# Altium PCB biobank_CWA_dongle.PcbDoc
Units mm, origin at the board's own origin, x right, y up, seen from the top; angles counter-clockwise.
Board outline 85 x 40 mm, 2 copper layers (Top Layer, Bottom Layer); 24 components, 27 nets, 138 pads, 60 vias.
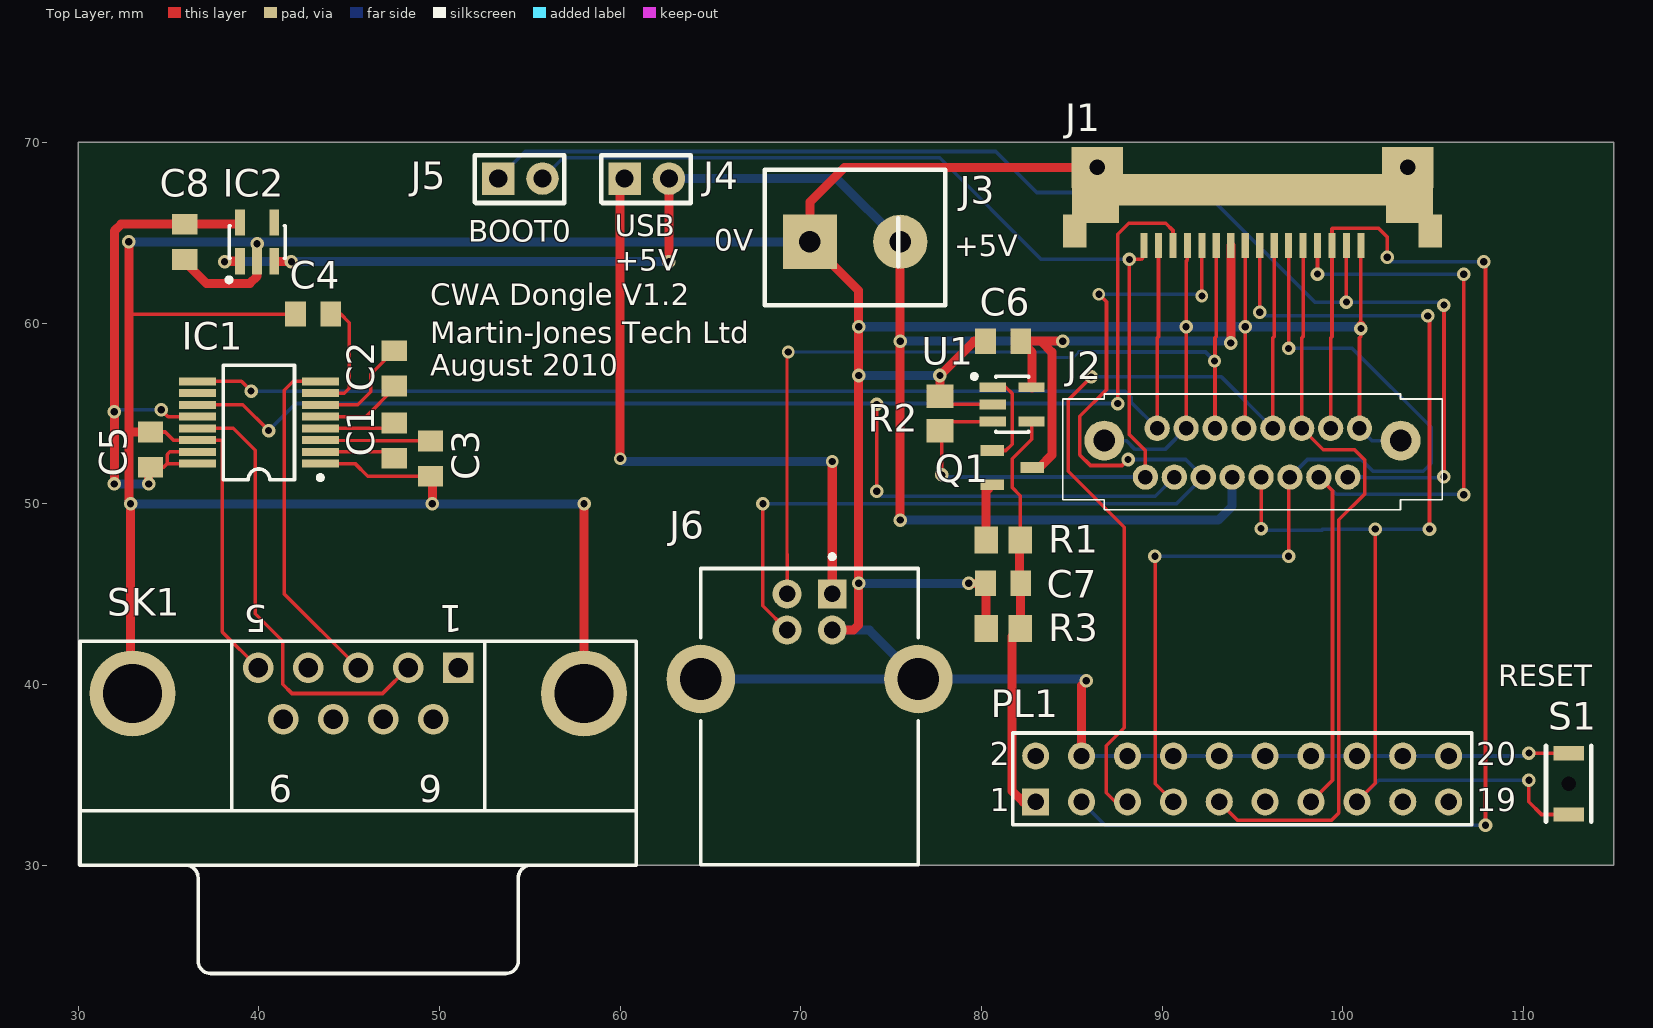
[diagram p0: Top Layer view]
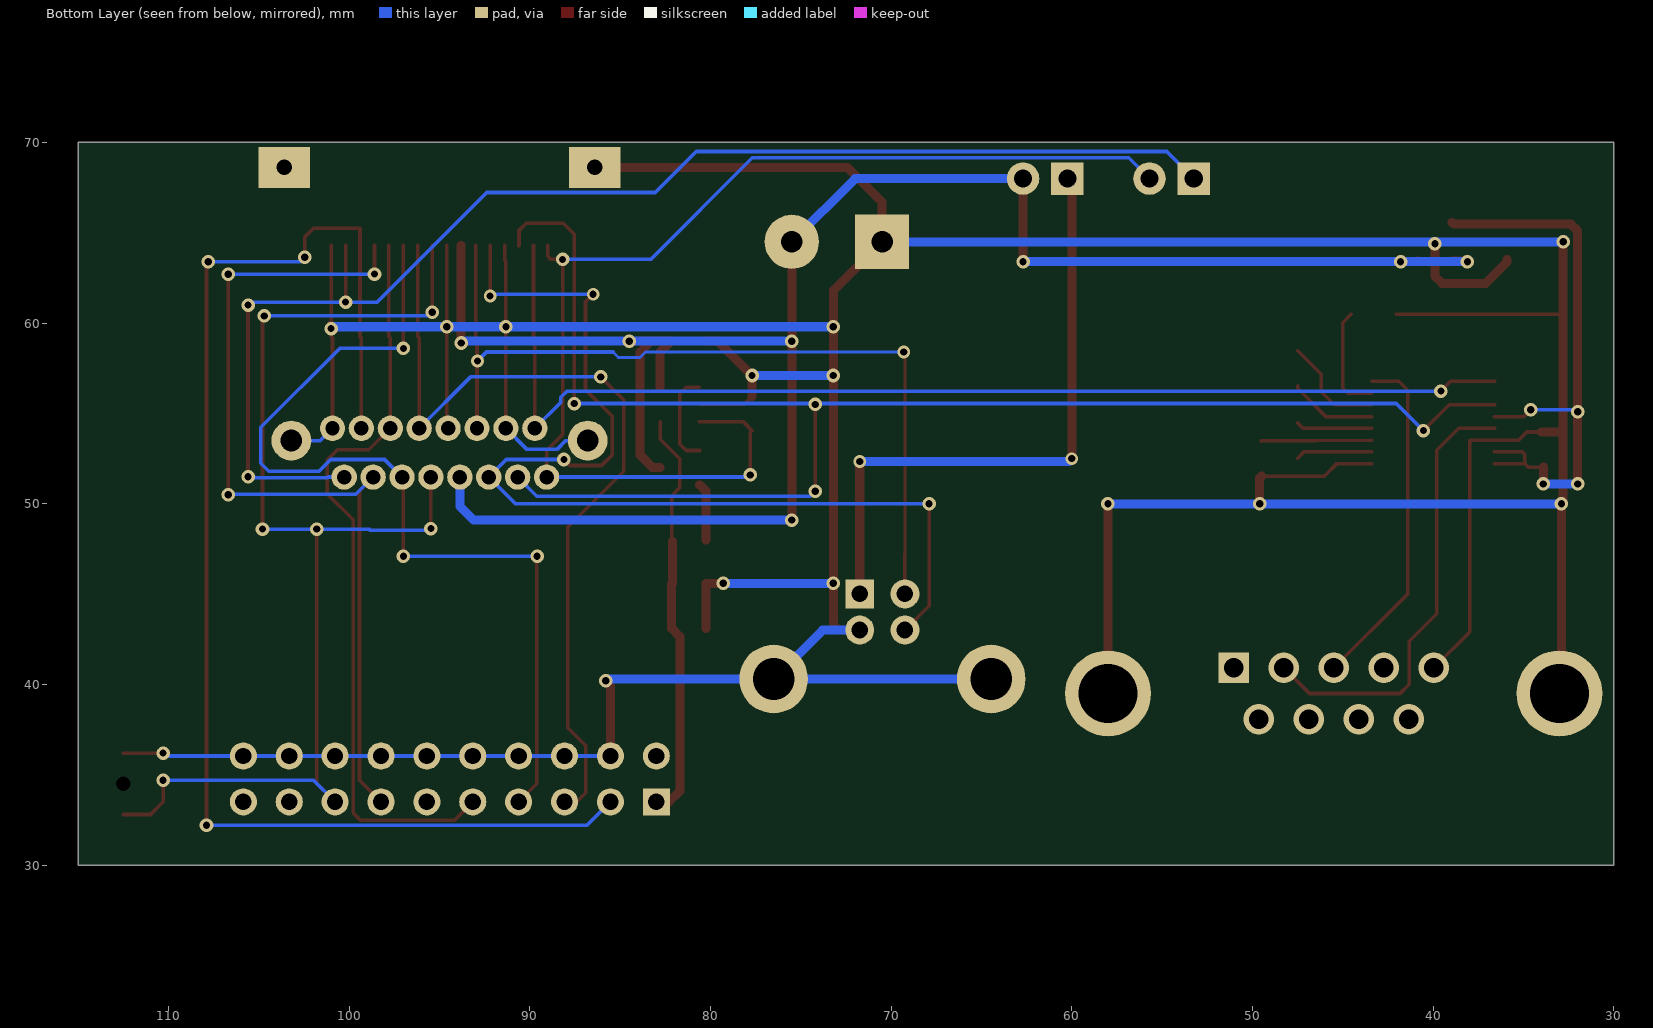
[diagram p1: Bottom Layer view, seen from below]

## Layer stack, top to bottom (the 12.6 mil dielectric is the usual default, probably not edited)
Top Layer: signal copper 0.0356
Dielectric: dielectric 0.32, FR-4, Dk 4.8
Bottom Layer: signal copper 0.0356

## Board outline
30,30 115,30 115,70 30,70

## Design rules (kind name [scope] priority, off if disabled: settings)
Clearance [All] p1: gap=0.15
FabricationTestPointUsage TestPointUsage [All] p1: valid=0 allowmultiple=FALSE
FabricationTestpoint Testpoint [All] p1: side=3 testpointundercomponent=TRUE minsize=1.016 maxsize=2.54 preferedsize=1.524 minholesize=0 maxholesize=1.016 preferedholesize=0.813 testpointgrid=0.025 allowsidetop=TRUE allowsidebottom=TRUE usegrid=TRUE gridtolerance=0
HoleSize [All] p1: absolutevalues=TRUE maxlimit=4 minlimit=0.025 maxpercent=80.000 minpercent=20.000
PolygonConnect [All] p1: connectstyle=Relief reliefconductorwidth=0.254 reliefentries=4 polygonreliefangle="90 Angle"
RoomDefinition biobank_CWA_dongle [InComponentClass('biobank_CWA_dongle')] p1: confinementstyle=ConfineIn formatcopy=TRUE lockcomponents=FALSE outline 29,23 115,23 115,71 29,71
RoutingVias [All] p1: holewidth=0.4 width=0.75 viastyle="Through Hole" minholewidth=0.3 minwidth=0.5 maxholewidth=0.8 maxwidth=1.5
SilkscreenOverComponentPads [All] p1: minsilkscreentomaskgap=0.254
SolderMaskExpansion [All] p1: expansion=0.102
Width [All] p1: maxlimit=1 minlimit=0.15 preferedwidth=0.5 bottomlayer_prefwidth=0.15 minimp=50.000000 maximp=50.000000 favimp=50.000000
24 further rules are at their usual default settings.

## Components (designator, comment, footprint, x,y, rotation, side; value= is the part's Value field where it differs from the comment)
C1 "" 0805-NP 47.5,53.5 r270 top
C2 "" 0805-NP 47.5,57.5 r90 top
C3 "" 0805-NP 49.5,52.5 r90 top
C4 "" 0805-NP 43,60.5 r180 top
C5 "" 0805-NP 34,53 r90 top
C6 "" 0805-NP 81.2,59 r0 top
C7 "" 0805-NP 81.2,45.6 r0 top
C8 "C_0805_4u7_X5R" 0805-NP 35.9,64.5 r90 top
IC1 "*" SSO-G16/X.45 40,54.5 r90 top
IC2 "TPS76333DBVT" SOT23-5 39.9,64.5 r0 top
J1 "CONN_HANDYLINK_16_0.8_MOLEX" HANDYLINK_16 95,65 r0 top
J2 "CONN_HANDYLINK_MALE_16_0.8_MOLEX" MOLEX_4559316xx 95,53.5 r0 top
J3 "*" 2WAY_5MM_TERMINAL 73,64.5 r0 top
J4 "CONN_2_PIN_0.1" 2WAY_0.1 61.5,68 r0 top
J5 "CONN_2_PIN_0.1" 2WAY_0.1 54.5,68 r0 top
J6 "USB slave" USB_B 70.5,44 r270 top
PL1 "" HDR2X10 83,33.5 r0 top
Q1 "BSS138N" SOT23-3 81.7,52 r270 top
R1 "R_0R_0805_1_MULTICOMP" CR2012-0805 81.2,48 r180 top
R2 "R_1M0_0805_1_MULTICOMP_1" CR2012-0805 77.7,55 r270 top
R3 "R_10K_0805_1_MULTICOMP" CR2012-0805 81.2,43.1 r0 top
S1 "" OMRON_B3U_B 112.5,34.5 r270 top
SK1 "" DSUB1.385-2H9 45.5,30 r180 top
U1 "FAN4174" SOT23-5 81.7,55.5 r270 top

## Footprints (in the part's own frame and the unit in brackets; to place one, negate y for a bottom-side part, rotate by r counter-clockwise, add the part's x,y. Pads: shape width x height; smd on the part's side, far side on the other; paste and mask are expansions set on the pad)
2WAY_0.1 [mm]
  rect 1.8x1.8 hole 1: 1(-1.25,0)
  round 1.8 hole 1: 2(1.2,0)
  silkscreen extent -2.55,-1.35 2.4,1.3
2WAY_5MM_TERMINAL [mm]
  rect 3x3 hole 1.2: 1(-2.5,0)
  round 3 hole 1.2: 2(2.5,0)
  silkscreen extent -5,-3.5 5,4
0805-NP [mm]
  rect 1.15x1.4 smd: 1(-0.975,0) 2(0.975,0)
CR2012-0805 [mm] "Chip Resistor; Body 2.0 x 1.3 mm (LxW typ)"
  rect 1.3x1.5 smd: 1(-0.95,0) 2(0.95,0)
DSUB1.385-2H9 [mm] "Connector; D Subminiature; 9 Position; Right Angle; Pitch 1.385 mm"
  rect 1.69x1.69 hole 1.09: 1(-5.54,-10.92)
  round 1.69 hole 1.09: 2(-2.77,-10.92) 3(0,-10.92) 4(2.77,-10.92) 5(5.54,-10.92) 6(-4.155,-8.08) 7(-1.385,-8.08) 8(1.385,-8.08) 9(4.155,-8.08)
  round 4.76 hole 3.26: 10(-12.495,-9.5) 11(12.495,-9.5)
  silkscreen extent -15.4,-12.4 15.4,6
HANDYLINK_16 [mm]
  rect 0.4x1.4 smd: 1(-6,-0.7) 2(-5.2,-0.7) 3(-4.4,-0.7) 4(-3.6,-0.7) 5(-2.8,-0.7) 6(-2,-0.7) 7(-1.2,-0.7) 8(-0.4,-0.7) 9(0.4,-0.7) 10(1.2,-0.7) 11(2,-0.7) 12(2.8,-0.7) 13(3.6,-0.7) 14(4.4,-0.7) 15(5.2,-0.7) 16(6,-0.7)
  rect 14.8x1.75 smd: PAD1(0,2.375)
  rect 2.6x2.95 smd: PAD2(-8.7,2.025) PAD4(8.7,2.025)
  rect 1.3x1.8 smd: PAD3(-9.85,0.1) PAD5(9.85,0.1)
  rect 2.85x2.26 hole 0.85: TAG1(-8.6,3.62) TAG2(8.6,3.62)
HDR2X10 [mm] "Connector; Header; 10x2 Position"
  rect 1.5x1.5 hole 0.9: 1(0,0)
  round 1.5 hole 0.9: 2(0,2.54) 3(2.54,0) 4(2.54,2.54) 5(5.08,0) 6(5.08,2.54) 7(7.62,0) 8(7.62,2.54) 9(10.16,0) 10(10.16,2.54) 11(12.7,0) 12(12.7,2.54) 13(15.24,0) 14(15.24,2.54) 15(17.78,0) 16(17.78,2.54) 17(20.32,0) 18(20.32,2.54) 19(22.86,0) 20(22.86,2.54)
  silkscreen extent -1.27,-1.27 24.13,3.81
MOLEX_4559316xx [mm] "Molex Handylink plug, PCB mounting"
  round 1.4 hole 0.8: 1(-5.925,-2.02) 2(-5.275,0.68) 3(-4.325,-2.02) 4(-3.675,0.68) 5(-2.725,-2.02) 6(-2.075,0.68) 7(-1.125,-2.02) 8(-0.475,0.68) 9(0.475,-2.02) 10(1.125,0.68) 11(2.075,-2.02) 12(2.725,0.68) 13(3.675,-2.02) 14(4.325,0.68) 15(5.275,-2.02) 16(5.925,0.68)
  round 2.2 hole 1.2: P1(-8.2,0) P2(8.2,0)
  silkscreen extent -10.5,-3.82 10.5,2.57
OMRON_B3U_B [mm]
  round 0 hole 0.8 unplated: 0(0,0)
  rect 0.8x1.7 smd: 1(-1.7,0) 2(1.7,0)
  silkscreen extent -2.1,-1.25 2.1,1.25
SOT23-3 [mm] "SOT-23; 3 Leads; Body 3.0 x 2.6 mm, inc. leads (LxW max)"
  rect 0.6x1.3 smd: 1(-0.95,-1.1) 2(0.95,-1.1) 3(0,1.1)
SOT23-5 [mm] "SOT-23/SC-74A; 5 Leads; Body 3.1 x 3 mm, inc. leads (LxW max)"
  rect 0.55x1.45 smd: 1(-0.95,-1.075) 2(0,-1.075) 3(0.95,-1.075) 4(0.95,1.075) 5(-0.95,1.075)
  silkscreen extent -1.67,-2.22 1.55,0.9
SSO-G16/X.45 [mm]
  rect 0.45x2.05 smd: 1(-2.275,-3.4) 2(-1.625,-3.4) 3(-0.975,-3.4) 4(-0.325,-3.4) 5(0.325,-3.4) 6(0.975,-3.4) 7(1.625,-3.4) 8(2.275,-3.4) 9(2.275,3.4) 10(1.625,3.4) 11(0.975,3.4) 12(0.325,3.4) 13(-0.325,3.4) 14(-0.975,3.4) 15(-1.625,3.4) 16(-2.275,3.4)
  silkscreen extent -3.17,-3.52 3.18,1.97
USB_B [mm] "USB slave socket"
  rect 1.6x1.6 hole 0.92: 1(-1.01,1.238)
  round 1.6 hole 0.92: 2(-1.01,-1.262) 3(0.99,-1.262) 4(0.99,1.238)
  round 3.8 hole 2.3: 5(3.7,6.008) 6(3.7,-6.032)
  silkscreen extent -3.2,-6.03 13.98,6.01

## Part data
C1 C2 C3 C4 C5 C6 C7: library part C_0805_100n_X7R, "Capacitor"
C8: "Capacitor"
IC1: library part MAX3221CDBE4
J1: "Molex Handylink 16 way 0.8mm Female"
J2: "Molex Handylink 16 way 0.8mm male"
J3: library part CONN_2_PIN_5MM_TERM, "2 way 5mm screw terminal"
J4: "2 pin 0.1in header"
J6: library part CONN_USB_SLAVE, "USB Slave connector"
PL1: library part CONN_10X2, "Header, 10-Pin, Dual row"
Q1: "N-Channel MOSFET"
S1: library part SW-NO-OMRON-B3U-1000P-B, "Switch"
SK1: library part CONN_DB9_FEMALE, "Receptacle Assembly, 9 Position, Right Angle"
U1: "Operational Amplifier"

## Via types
v1: diameter 0.75, hole 0.4, Top Layer to Bottom Layer, 54 vias
v2: diameter 0.7, hole 0.4, Top Layer to Bottom Layer, 6 vias

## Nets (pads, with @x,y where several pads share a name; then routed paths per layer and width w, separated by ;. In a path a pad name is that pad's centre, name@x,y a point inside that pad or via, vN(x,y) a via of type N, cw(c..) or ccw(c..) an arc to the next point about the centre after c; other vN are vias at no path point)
BOOT0: J1.15 J2.15 J5.1 | length 74.5
  Top Layer w0.2: v1(100.2,61.163) J1.15 ; v1(105.6,51.5) v1(105.6,61)
  Bottom Layer w0.2: J5.1 54.75,69.5 80.792,69.5 83.058,67.234 92.392,67.234 98.463,61.163 105.437,61.163 v1(105.6,61) ; J2.15 101.15,51.48 101.18,51.45 105.214,51.45 v1@105.25,51.486 ; v1@105.25,51.5 v1(105.6,51.5)
D+EXT: J1.5 J2.5 J6.3 | length 58.4
  Top Layer w0.2: v1(67.9,50) 67.9,44.349 J6.3 ; v2(86.5,61.6) 86.919,61.181 86.919,56.312 85.446,54.839 85.446,52.705 86.03,52.121 87.782,52.121 v1(88.113,52.451) ; v2(92.2,61.5) J1.5
  Bottom Layer w0.2: v1(67.9,50) 90.795,50 J2.5 91.304,52.451 v1(88.113,52.451) ; v2(86.5,61.6) 92.1,61.6 v2(92.2,61.5)
D-EXT: J1.6 J2.6 J6.2 | length 47.6
  Top Layer w0.15: 69.238,47.2 69.238,58.338 v2(69.3,58.4)
  Top Layer w0.2: J6.2 69.238,47.2 ; J2.6 92.925,59.182 93,59.257 J1.6
  Bottom Layer w0.15: v2(69.3,58.4) 83.6,58.4 83.9,58.1 85.1,58.1 85.4,58.4
  Bottom Layer w0.2: 85.4,58.4 92.4,58.4 v2(92.9,57.9)
DRXD: IC1.9 J1.2 J2.2 | length 64.5
  Top Layer w0.2: IC1.9 39.034,56.775 v1(39.572,56.237) ; J2.2 89.725,59.182 89.8,59.257 J1.2
  Bottom Layer w0.2: v1(39.572,56.237) 87.947,56.237 88.293,55.891 88.293,55.612 J2.2
DTXD: IC1.11 J1.3 J2.3 | length 87.7
  Top Layer w0.2: IC1.11 39.116,55.475 v1(40.54,54.051) ; v1(74.2,50.7) v1(74.2,55.5) ; v1(87.538,55.55) 87.538,64.915 88.155,65.532 90.195,65.532 90.6,65.127 J1.3
  Bottom Layer w0.2: v1(40.54,54.051) 42.038,55.55 v1(87.538,55.55) ; v1(74.2,50.7) 74.481,50.419 89.614,50.419 J2.3
EXT_RXD: IC1.8 SK1.3 | length 19.2
  Top Layer w0.2: IC1.8 41.91,56.775 41.413,56.278 41.413,45.007 SK1.3
EXT_TXD: IC1.13 SK1.2 | length 25
  Top Layer w0.2: IC1.13 38.583,54.175 39.802,52.956 39.802,43.917 41.326,42.393 41.326,40.005 41.834,39.497 46.847,39.497 SK1.2
GND: C3.1 C4.2 C5.2 C6.1 C7.1 C8.1 IC1.1 IC1.14 IC2.2 J1.4 J1.8 J1.16 J1.PAD1 J1.PAD2 J1.PAD3 J1.PAD4 J1.PAD5 J1.TAG1 J1.TAG2 J2.4 J2.8 J2.16 J2.P1 J2.P2 J3.1 J6.4 J6.5 J6.6 PL1.4 PL1.6 PL1.8 PL1.10 PL1.12 PL1.14 PL1.16 PL1.18 PL1.20 R2.1 R3.1 S1.1 SK1.5 SK1.10 SK1.11 U1.2 | length 330.5
  Top Layer w0.2: 32.8,60.5 C4.2 ; C5.2@33.5,53.975 34.823,53.975 35.273,53.525 IC1.14 37.948,53.525 37.973,53.5 37.973,42.907 SK1.5 ; IC1.1 45.325,52.225 46.025,51.525 C3.1 ; R2.1 78.15,55.5 U1.2 ; J2.4 91.325,63.425 91.4,63.5 J1.4 ; J2.8 94.6,54.255 v1(94.6,59.8) 94.6,60.3 J1.8 ; J2.16 100.925,59.182 101,59.257 v1(101,59.7) ; v1@101,59.9 J1.16 ; v1(110.3,36.2) 110.7,36.2 S1.1
  Top Layer w0.5: 32.8,54.1 32.925,53.975 C5.2 ; v1(32.8,64.5) 32.8,50.1 v1(32.9,50) 32.9,39.605 SK1.11 ; C8.1 35.9,63.4 37.1,62.2 39.5,62.2 39.9,62.6 v1(39.9,64.4) ; C3.1 49.6,51.425 v1(49.6,50) ; SK1.10 58,39.505 v1(58,50) ; J6.4 72.91,43.01 73.2,43.3 73.2,61.8 J3.1 70.5,66.7 72.42,68.62 J1.TAG1 J1.TAG1@86.42,68.6 ; R2.1 v1(77.7,57.1) 79.6,59 C6.1 ; v1(79.3,45.6) C7.1 80.25,45.575 R3.1 ; PL1.4 85.54,39.94 v1(85.8,40.2) ; v1(101,59.7) v1@101,59.9
  Bottom Layer w0.2: PL1.4 PL1.6 PL1.8 PL1.10 PL1.12 PL1.14 PL1.16 PL1.18 110.14,36.04 v1(110.3,36.2) ; J2.P1 88.011,53.5 88.501,53.01 90.155,53.01 J2.4 ; J2.16 101.605,53.5 J2.P2
  Bottom Layer w0.5: v1(32.8,64.5) J3.1 ; v1(32.9,50) v1(58,50) ; J6.6 85.7,40.3 v1(85.8,40.2) ; J6.4 73.798,43.01 J6.5 ; v1(73.2,45.6) v1(79.3,45.6) ; v1(73.2,57.1) v1(77.7,57.1) ; v1(73.2,59.8) 100.9,59.8 v1(101,59.7)
  other v1: 91.325,59.8
NetC1_1: C1.1 IC1.4 | length 4.2
  Top Layer w0.2: IC1.4 47.2,54.175 C1.1
NetC1_2: C1.2 IC1.2 | length 4.2
  Top Layer w0.2: IC1.2 47.15,52.875 C1.2
NetC2_1: C2.1 IC1.5 | length 4.9
  Top Layer w0.2: IC1.5 45.925,54.825 47.5,56.4 C2.1
NetC2_2: C2.2 IC1.6 | length 5.9
  Top Layer w0.2: IC1.6 45.475,55.475 46.2,56.2 46.2,57.175 C2.2
NetC3_2: C3.2 IC1.3 | length 6.1
  Top Layer w0.2: IC1.3 C3.2
NetC4_1: C4.1 IC1.7 | length 6
  Top Layer w0.2: IC1.7 44.725,56.125 45,56.4 45,60.025 C4.1@44.525,60.5
NetJ4_1: J4.1 J6.1 | length 34.7
  Top Layer w0.5: v2(60,52.5) 60,67.75 J4.1 ; J6.1 v2(71.738,52.338)
  Bottom Layer w0.5: v2(60,52.5) 60.162,52.338 v2(71.738,52.338)
NetQ1_2: Q1.1 U1.1 | length 5.3
  Top Layer w0.2: Q1.1 81.35,52.95 81.7,53.3 81.7,56.1 81.35,56.45 U1.1
NetQ1_3: Q1.2 R1.2 | length 3.2
  Top Layer w0.5: R1.2 80.25,50.7 Q1.2
NRST: J1.9 J2.9 PL1.15 S1.2 | length 66.4
  Top Layer w0.2: v1(95.4,60.6) 95.4,61.9 J1.9 ; v1(95.475,48.625) J2.9 ; PL1.15 101.803,34.523 101.803,48.597 v1(101.8,48.6) ; v1(104.7,60.4) 104.8,60.3 v1(104.8,48.6) ; v1(110.3,34.7) 110.3,33.5 111,32.8 S1.2
  Bottom Layer w0.2: v1@95.4,48.6 v1@95.475,48.6 ; v1(95.4,60.6) 95.6,60.4 v1(104.7,60.4) ; v1@95.475,48.525 98.825,48.525 98.9,48.6 v1(104.8,48.6) ; PL1.15 101.98,34.7 v1(110.3,34.7)
TCK: J1.12 J2.12 PL1.9 | length 41.7
  Top Layer w0.2: PL1.9 94.173,32.487 99.377,32.487 99.78,32.889 99.78,49.116 101.225,50.561 101.225,52.407 100.647,52.984 98.92,52.984 J2.12 97.725,59.182 97.8,59.257 J1.12
TDI: J1.10 J2.10 PL1.5 | length 48
  Top Layer w0.2: v1(86.081,57.023) 84.8,55.742 84.8,51.8 87.9,48.7 87.9,37.6 86.9,36.6 86.9,34 87.4,33.5 PL1.5 ; J2.10 96.125,59.182 96.2,59.257 J1.10
  Bottom Layer w0.2: v1(86.081,57.023) 93.282,57.023 J2.10
TDO: J1.13 J2.13 PL1.13 | length 49.1
  Top Layer w0.2: PL1.13 99.43,34.69 99.43,50.725 J2.13 ; v1(98.6,62.713) J1.13 ; v1(106.7,50.5) v1(106.7,62.7)
  Bottom Layer w0.2: v1(98.6,62.713) 106.687,62.713 v1(106.7,62.7) ; J2.13 99.634,50.521 106.679,50.521 v1(106.7,50.5)
TMS: J1.11 J2.11 PL1.7 | length 51.9
  Top Layer w0.2: v1(89.6,47.1) 89.611,47.089 89.611,34.509 PL1.7 ; v1(97,47.1) 97,51.405 J2.11 ; v1(97,58.6) J1.11
  Bottom Layer w0.2: v1(89.6,47.1) v1(97,47.1) ; v1(97,58.6) 100.531,58.6 104.9,54.231 104.9,52.242 104.457,51.8 101.667,51.8 101.016,52.451 98.046,52.451 J2.11
TRST: J1.14 J2.14 PL1.3 | length 75.1
  Top Layer w0.2: J2.14 99.325,59.182 99.4,59.257 J1.14 99.4,65.227 99.425,65.253 101.981,65.253 102.464,64.77 v1(102.464,63.652) ; v1(107.8,63.4) 107.9,63.3 v1(107.9,32.2)
  Bottom Layer w0.2: PL1.3 86.84,32.2 v1(107.9,32.2) ; v1(102.464,63.652) 102.716,63.4 v1(107.8,63.4)
USB_VBUS: C6.2 IC2.1 IC2.3 J1.7 J2.7 J3.2 J4.2 Q1.3 U1.5 | length 117.8
  Top Layer w0.5: v1(38.1,63.4) 38.125,63.425 IC2.1 ; IC2.3 40.875,63.4 v1(41.8,63.4) ; v1(62.7,63.4) J4.2 ; v1(75.5,49.1) J3.2 ; Q1.3 83.2,52 83.9,52.7 83.9,58.4 83.3,59 ; U1.5@82.8,56.4 82.8,58.375 C6.2 v1(84.5,59) ; v1(93.8,58.9) 93.8,60.5 J1.7
  Bottom Layer w0.5: v1(38.1,63.4) v1(62.7,63.4) ; J4.2 72,68 J3.2 ; v1(75.5,49.1) 93.1,49.1 93.875,49.875 J2.7 ; v1(75.5,59) 93.7,59 v1(93.8,58.9)
VDD_3V3: C5.1 C8.2 IC1.12 IC1.15 IC1.16 IC2.5 | length 33.7
  Top Layer w0.2: C5.1 34.725,52.025 34.925,52.225 ; v1(34.6,55.2) 34.975,54.825 IC1.12 ; IC1.16 34.925,52.225 ; IC1.15 35.075,52.875 34.925,52.725 34.925,52.225
  Top Layer w0.5: v1(32,51.1) 32,65.1 32.375,65.475 38.85,65.475 IC2.5 ; v1(33.9,51.1) C5.1@33.9,52.025
  Bottom Layer w0.2: v1(32,55.1) 32.1,55.2 v1(34.6,55.2)
  Bottom Layer w0.5: v1(32,51.1) v1(33.9,51.1)
VDD_CPU: J1.1 J2.1 J5.2 R2.2 U1.3 | length 66
  Top Layer w0.2: R2.2 78.2,54.55 U1.3 ; v1(77.8,51.6) R2.2@77.8,53.95 ; J1.1 89,63.7 88.825,63.525 v1(88.189,63.525) 88.189,53.823 89.075,52.936 J2.1
  Bottom Layer w0.2: J5.2 56.85,69.15 77.687,69.15 83.312,63.525 v1(88.189,63.525) ; v1(77.8,51.6) 77.92,51.48 J2.1
VREF: C7.2 PL1.1 R1.1 R3.2 U1.4 | length 22.7
  Top Layer w0.2: R1.1 82.15,50.45 81.7,50.9 81.7,52.5 82.775,53.575 U1.4
  Top Layer w0.5: R1.1@82.1,47.9 82.1,45.6 82.15,45.55 R3.2 81.7,42.65 81.7,34.1 82.3,33.5 PL1.1
pads on no net: IC1.10 IC2.4 PL1.2 PL1.11 PL1.17 PL1.19 S1.0 SK1.1 SK1.4 SK1.6 SK1.7 SK1.8 SK1.9

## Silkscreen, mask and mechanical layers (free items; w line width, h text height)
Top Overlay:
  text "USB" at 59.7,64.8 h1.2
  text "BOOT0" at 51.6,64.5 h1.2
  text "0V" at 65.2,64 h1.2
  text "+5V" at 78.5,63.7 h1.2
  text "+5V" at 59.7,62.9 h1.2
  text "CWA Dongle V1.2" at 49.5,61 h1.2
  text "Martin-Jones Tech Ltd" at 49.5,58.9 h1.2
  text "August 2010" at 49.5,57.1 h1.2
  text "RESET" at 108.6,39.9 h1.2
Mechanical 1:
  the board outline again, w0.1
